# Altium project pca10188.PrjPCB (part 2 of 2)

## Sheet pca10188_sheet7_connectors.SchDoc: =BoardTitle+' - Connectors'
size A3; Organization: Nordic Semiconductor; DocumentNumber: 7; Revision: 0.7.0; SheetNumber: 7; SheetTotal: 7; Author: DABA; CompanyName: Nordic Semiconductor; DrawnBy: DABA; DocumentSize: A4
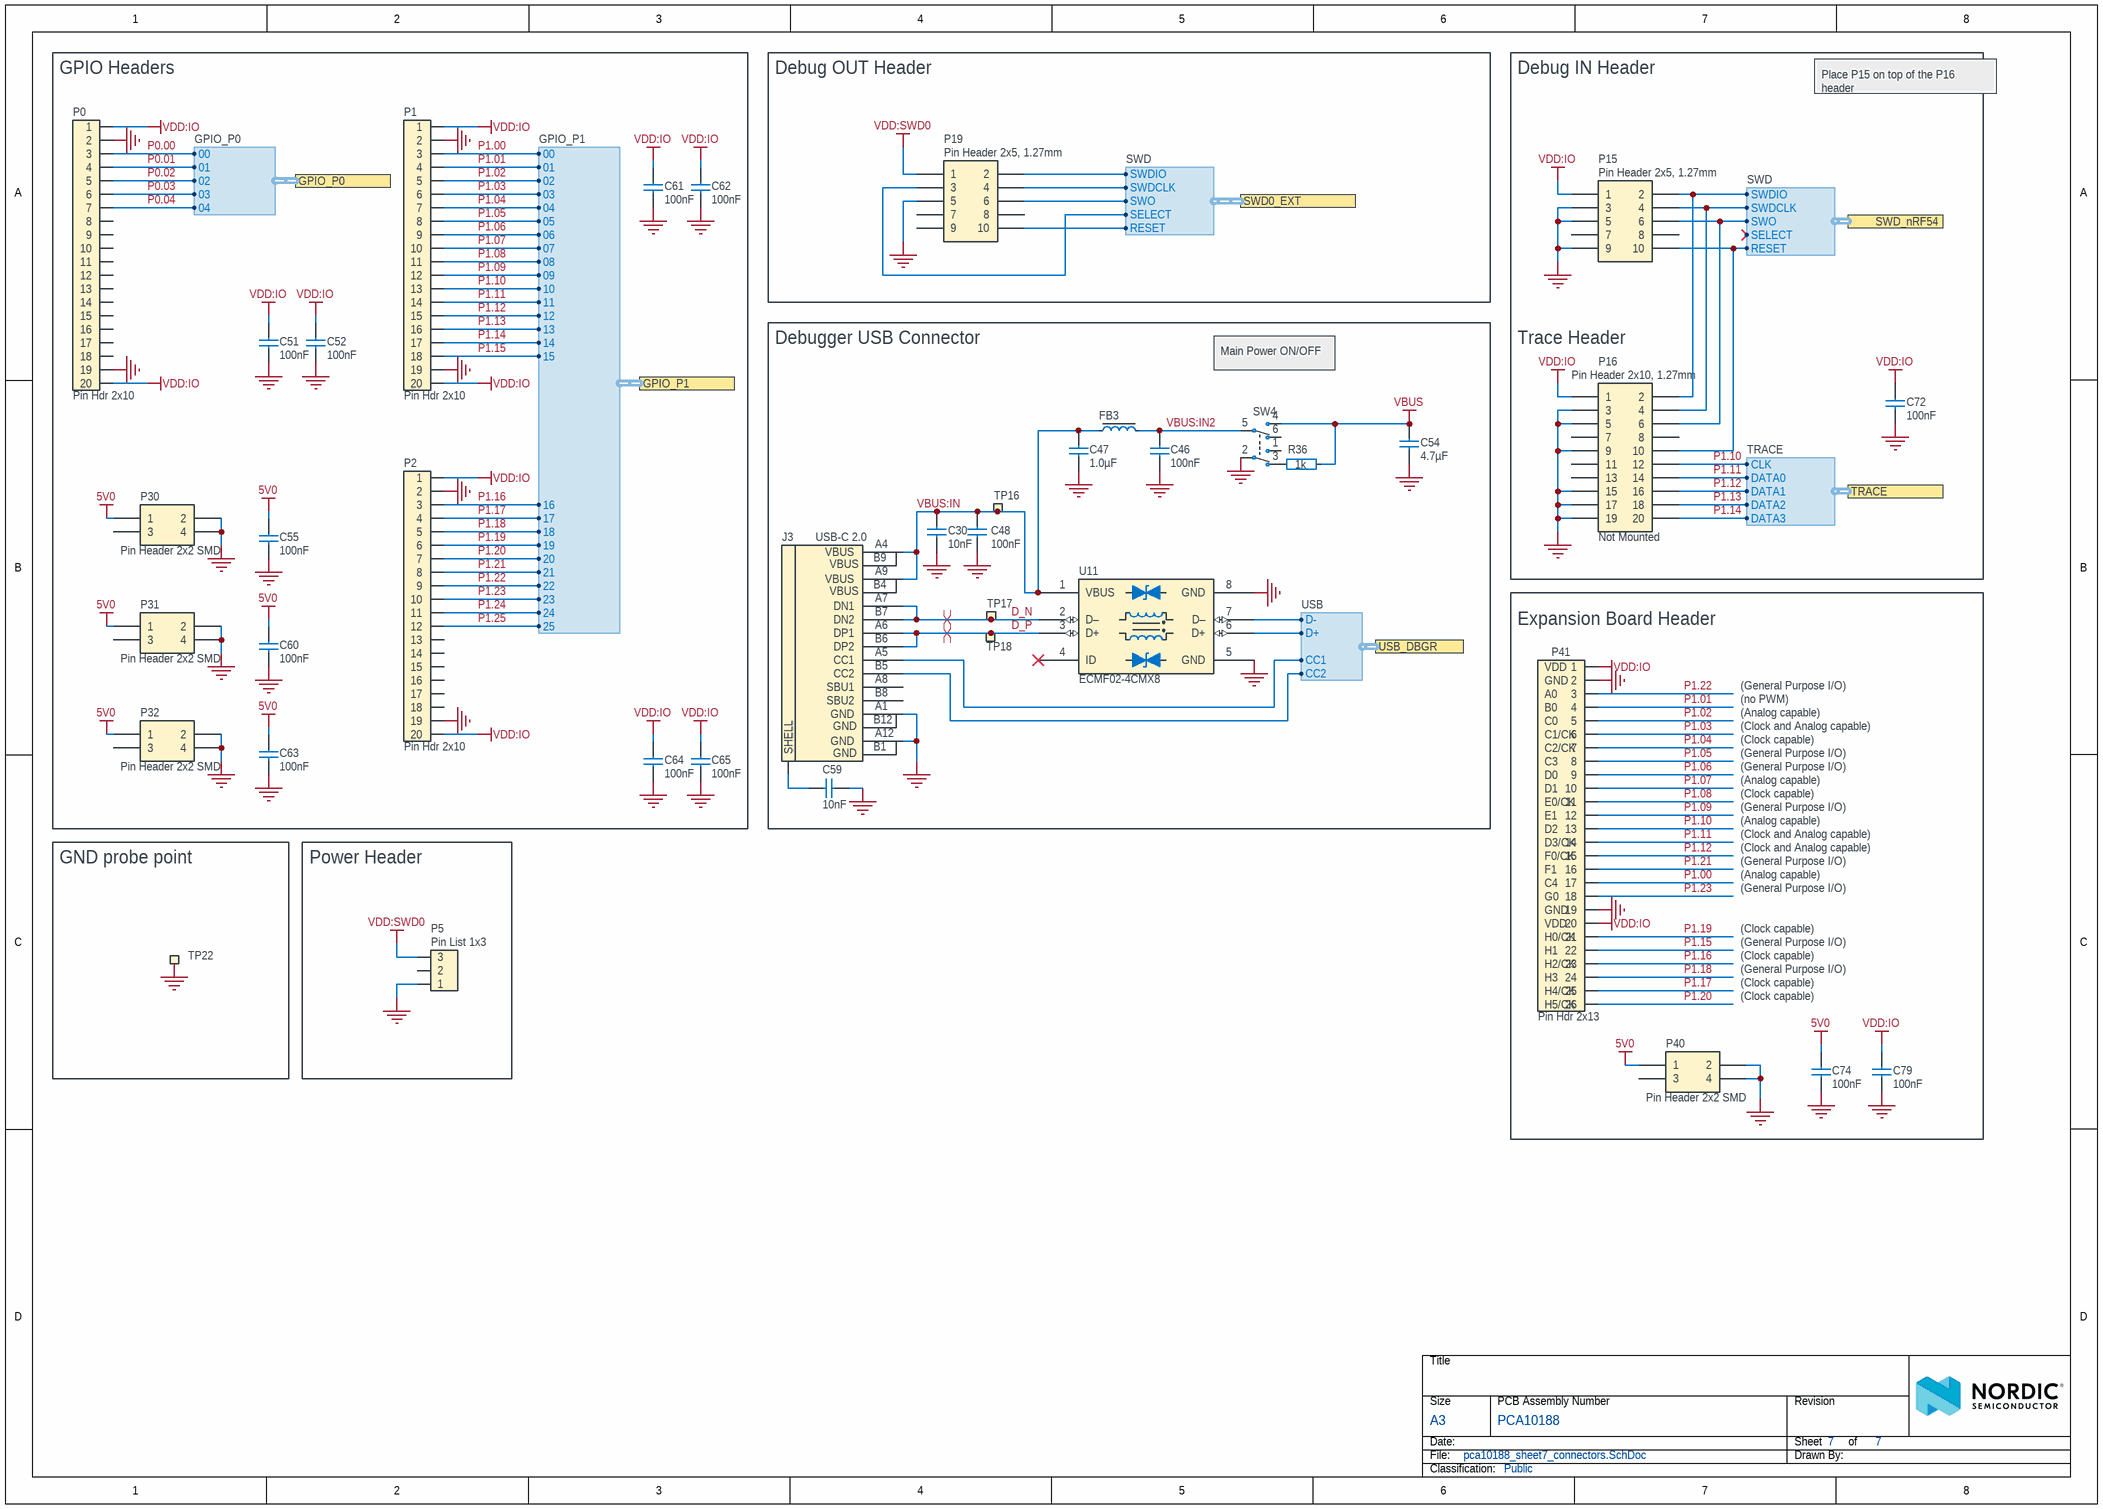
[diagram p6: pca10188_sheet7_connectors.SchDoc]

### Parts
C30  10nF  [CAPC0603X03L_C]
C46  100nF  [CAPC0603X03L_C]
C47  1.0µF  [CAPC1005X04L]
C48  100nF  [CAPC0603X03L_C]
C51  100nF  [CAPC0603X03L_C]
C52  100nF  [CAPC0603X03L_C]
C54  4.7µF  [CAPC1608X06L]
C55  100nF  [CAPC0603X03L_C]
C59  10nF  [CAPC1608X06L]
C60  100nF  [CAPC0603X03L_C]
C61  100nF  [CAPC0603X03L_C]
C62  100nF  [CAPC0603X03L_C]
C63  100nF  [CAPC0603X03L_C]
C64  100nF  [CAPC0603X03L_C]
C65  100nF  [CAPC0603X03L_C]
C72  100nF  [CAPC0603X03L_C]
C74  100nF  [CAPC0603X03L_C]
C79  100nF  [CAPC0603X03L_C]
FB3  120R/0.55A  [INDC1005X04L]  (value not drawn)
J3  USB-C 2.0  [SD-80259-001]
P0  Pin Hdr 2x10  [HDR_2x10-SMD]
P1  Pin Hdr 2x10  [HDR_2x10-SMD]
P2  Pin Hdr 2x10  [HDR_2x10-SMD]
P5  Pin List 1x3  [LIST_1x3_SMD]
P15  Pin Header 2x5, 1.27mm  [HDR_2x5-SMD-1.27mm-K]
P16  Pin Header 2x10, 1.27mm  Assembly: Not Mounted  [HDR_2x10-SMD-1.27mm-NC]
P19  Pin Header 2x5, 1.27mm  [HDR_2x5-SMD-1.27mm-K]
P30  Pin Header 2x2 SMD  [HDR_2x2-SMD]
P31  Pin Header 2x2 SMD  [HDR_2x2-SMD]
P32  Pin Header 2x2 SMD  [HDR_2x2-SMD]
P40  Pin Header 2x2 SMD  [HDR_2x2-SMD]
P41  Pin Hdr 2x13  [HDR_2x13-SMD]
R36  1k  [RESC0603X03L_C]
SW4  Switch  [JS102011JAQN]  (value not drawn)
TP16  Ø1.5mm,SMD  [TP_SMD_D1.5mm]  (value not drawn)  (no BOM)
TP17  Ø1.5mm,SMD  [TP_SMD_D1.5mm]  (value not drawn)  (no BOM)
TP18  Ø1.5mm,SMD  [TP_SMD_D1.5mm]  (value not drawn)  (no BOM)
TP22  TP  [S1751]  (value not drawn)
U11  ECMF02-4CMX8  [UFDFN50P120X250X55-8N]

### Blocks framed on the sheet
GPIO Headers: C51 C52 C55 C60-C65 P0-P2 P30-P32
Debug OUT Header: P19
Debugger USB Connector: C30 C46-C48 C54 C59 FB3 J3 R36 SW4 TP16-TP18 U11
Expansion Board Header: C74 C79 P40 P41
GND probe point: TP22
Power Header: P5

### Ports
GPIO_P0 (harness GPIO_P0), GPIO_P1 (harness GPIO_P1), SWD0_EXT (harness SWD), SWD_nRF54 (harness SWD), TRACE (harness TRACE), USB_DBGR (harness USB)

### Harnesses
SWD: SWDIO, SWDCLK, SWO, RESET, SELECT
TRACE: CLK, DATA0, DATA1, DATA3, DATA2
GPIO_P0: 02, 03, 04, 00, 01
USB: D+, D-, CC1, CC2
GPIO_P1: 00, 01, 02, 03, 04, 05, 06, 07, 08, 09, 10, 11, 12, 13, 14, 15, 21, 22, 16, 23, 17, 24, 18, 25, 19, 20

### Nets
5V0: C55.2 C60.2 C63.2 C74.2 P30.1 P31.1 P32.1 P40.1
GND: C30.2 C46.1 C47.1 C48.1 C51.1 C52.1 C54.2 C55.1 C59.2 C60.1 C61.1 C62.1 C63.1 C64.1 C65.1 C72.1 C74.1 C79.1 J3.A1(GND) J3.A12(GND) P0.2 P0.19 P1.2 P1.19 P2.2 P2.19 P5.1 P15.3 P15.5 P15.9 P16.3 P16.5 P16.9 P16.15 P16.17 P16.19 P19.5 P30.2 P30.4 P31.2 P31.4 P32.2 P32.4 P40.2 P40.4 P41.2 P41.19 SW4.2(COM-1) TP22.1 U11.5(GND) U11.8(GND)
VBUS: C54.1 R36.2 SW4.4(N.O-2)
VDD:IO: C51.2 C52.2 C61.2 C62.2 C64.2 C65.2 C72.2 C79.2 P0.1 P0.20 P1.1 P1.20 P2.1 P2.20 P15.1 P16.1 P41.1 P41.20
VDD:SWD0: P5.3 P19.1
D_N: J3.A7(DN1) J3.B7(DN2) TP17.1 U11.2(D–)
D_P: J3.A6(DP1) J3.B6(DP2) TP18.1 U11.3(D+)
DBGR_N: U11.7(D–) ; port USB_DBGR.D-
DBGR_P: U11.6(D+) ; port USB_DBGR.D+
nRF54_NRESET: P15.10 P16.10 ; port SWD_nRF54.RESET
P0.00: P0.3 ; port GPIO_P0.00
P0.01: P0.4 ; port GPIO_P0.01
P0.02: P0.5 ; port GPIO_P0.02
P0.03: P0.6 ; port GPIO_P0.03
P0.04: P0.7 ; port GPIO_P0.04
P1.00: P1.3 P41.17 ; port GPIO_P1.00
P1.01: P1.4 P41.4 ; port GPIO_P1.01
P1.02: P1.5 P41.5 ; port GPIO_P1.02
P1.03: P1.6 P41.6 ; port GPIO_P1.03
P1.04: P1.7 P41.7 ; port GPIO_P1.04
P1.05: P1.8 P41.8 ; port GPIO_P1.05
P1.06: P1.9 P41.9 ; port GPIO_P1.06
P1.07: P1.10 P41.10 ; port GPIO_P1.07
P1.08: P1.11 P41.11 ; port GPIO_P1.08
P1.09: P1.12 P41.12 ; port GPIO_P1.09
P1.10: P1.13 P16.12 P41.13 ; port TRACE.CLK, port GPIO_P1.10
P1.11: P1.14 P15.6 P16.6 P16.14 P41.14 ; port SWD_nRF54.SWO, port TRACE.DATA0, port GPIO_P1.11
P1.12: P1.15 P16.16 P41.15 ; port TRACE.DATA1, port GPIO_P1.12
P1.13: P1.16 P16.18 ; port TRACE.DATA2, port GPIO_P1.13
P1.14: P1.17 P16.20 ; port TRACE.DATA3, port GPIO_P1.14
P1.15: P1.18 P41.22 ; port GPIO_P1.15
P1.16: P2.3 P41.23 ; port GPIO_P1.16
P1.17: P2.4 P41.25 ; port GPIO_P1.17
P1.18: P2.5 P41.24 ; port GPIO_P1.18
P1.19: P2.6 P41.21 ; port GPIO_P1.19
P1.20: P2.7 P41.26 ; port GPIO_P1.20
P1.21: P2.8 P41.16 ; port GPIO_P1.21
P1.22: P2.9 P41.3 ; port GPIO_P1.22
P1.23: P2.10 P41.18 ; port GPIO_P1.23
P1.24: P2.11 ; port GPIO_P1.24
P1.25: P2.12 ; port GPIO_P1.25
SWD0_CLK_EXT: P19.4 ; port SWD0_EXT.SWDCLK
SWD0_IO_EXT: P19.2 ; port SWD0_EXT.SWDIO
SWD0_RESET_EXT: P19.10 ; port SWD0_EXT.RESET
SWD0_SEL: P19.3 ; port SWD0_EXT.SELECT
SWD0_SWO_EXT: P19.6 ; port SWD0_EXT.SWO
SWDCLK: P15.4 P16.4 ; port SWD_nRF54.SWDCLK
SWDIO: P15.2 P16.2 ; port SWD_nRF54.SWDIO
VBUS:IN: C30.1 C47.2 C48.2 FB3.1 J3.A4(VBUS) J3.A9(VBUS) TP16.1 U11.1(VBUS)
VBUS:IN2: C46.2 FB3.2 SW4.5(COM-2)
NetC59_1: C59.1 J3.SHLD(SHELL)
NetJ3_A5: J3.A5(CC1) ; port USB_DBGR.CC1
NetJ3_B5: J3.B5(CC2) ; port USB_DBGR.CC2
NetR36_1: R36.1 SW4.3(N.C-1)

Not connected (* = marked no-connect by the designer): J3 A8(SBU1) B8(SBU2); P0 8 9 10 11 12 13 14 15 16 17 18; P2 13 14 15 16 17 18; P5 2; P15 7 8; P16 7 8 11 13; P19 7 8 9; P30 3; P31 3; P32 3; P40 3; SW4 1(N.O-1) 6(N.C-2); U11 4(ID)*

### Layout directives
differential pair; differential pair class IMCU; net class IMCU_USB: D_N, D_P

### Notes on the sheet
- Debug IN Header
- Place P15 on top of the P16 header
- Main Power ON/OFF
- (near P16) Trace Header
- (near P41) VDD
- (near P41) GND
- (near P41) A0
- (near P41) B0
- (near P41) C0
- (Analog capable)
- (no PWM)
- (General Purpose I/O)
- (near P41) D0
- (near P41) D1
- (near P41) C1/CK
- (near P41) C2/CK
- (near P41) C3
- (Clock and Analog capable)
- (Clock capable)
- (near P41) E0/CK
- (near P41) E1
- (near P41) D2
- (near P41) D3/CK
- (near P41) F0/CK
- (near P41) F1
- (near P41) C4
- (near P41) G0
- (near P41) H0/CK
- (near P41) H1
- (near P41) H2/CK
- (near P41) H3
- (near P41) H4/CK
- (near P41) H5/CK

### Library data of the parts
C30 = C0201-10n: Capacitor, X7R, ±10%; Manufacturer: N.A.; Part number IPS: 00000003480; Part number Norautron: 26621779; Part number NEMS: 100200067; Note: 10V; Pad Count: 2; Component Status: Active
C46 C48 C51 C52 C55 C60-C65 C72 C74 C79 = C0201-100n: Capacitor, X5R, ±10%; Manufacturer: N.A.; Part number IPS: 00000001248, 00000002505; Part number Norautron: 262071862; Part number NEMS: 100200078; Note: 16V; Pad Count: 2; Component Status: Active
C47 = C0402-1µ0-16V-X5R: Capacitor, Ceramic, X5R, ±10%, 16V; Manufacturer: Murata; Manufacturer Part Number: GRT155R61C105KE01D; Part number NEMS: 100200452; Component Status: Active; Pad Count: 2; Artikkelnr Noca: N.A.
C54 = C0603-4µ7-10V-X7S: Capacitor, X7S, ±10%, 10V; Manufacturer: N.A.; Part number IPS: 00000001779; Part number NEMS: 100200351; Pad Count: 2; Artikkelnr Noca: 20030013; Component Status: Active
C59 = C0603-10n-100V-X7R: Capacitor, X7R, ±10%, 100V; Manufacturer: Murata; Manufacturer Part Number: GCM188R72A103KA37D; Part number NEMS: 100200349; Component Status: Active; Pad Count: 2; Artikkelnr Noca: N.A.
FB3 = FB0402-120R@100M-500mA: Ferrite Bead, 120 Ohm @ 100MHz, 500mA, 250 mOhm Max; Manufacturer: Murata; Manufacturer Part Number: BLM15AG121SN1D; Part number IPS: 00000009954; Part number Norautron: 265230631; Part number NEMS: 100300099; Note: Chip EMIFIL Inductor Type Chip Ferrite Bead; Artikkelnr Noca: 33029317; Pad Count: 2; Component Status: Active
J3 = 80259-1021: USB-C Receptacle, 16 Pin, USB 2.0; Manufacturer: Bellweather Electronic Corp.; Part number NEMS: 100500830; Component Status: Active; Pad Count: 16; Note: N.A.; System: Connector
P0-P2 = Pin Header 2x10 SMD, 2.54mm: Pin Header 2x10, 2.54mm (100mil) SMD; Manufacturer: WCON; Manufacturer Part Number: 1125-1210S0M116CR09; Part number NEMS: 100500738; Pad Count: 20; Artikkelnr Noca: N.A.; Component Status: Active; System: Connector
P5 = Pin List 1x3 SMD: Pin List 1x3, 2.54mm (100mil), SMD; Manufacturer: WCON; Manufacturer Part Number: 1125-1103S0M116CR04; Part number Norautron: 26470016; Part number NEMS: 100500306; Note: N.A.; Pad Count: 3; Component Status: Active; System: Connector
P15 P19 = Pin Header 2x5 SMD, 1.27mm, KS: Pin Header 2x5, 1.27mm (50mil), SMD, Keying Shroud; Manufacturer: WCON; Manufacturer Part Number: 3132-10MS0BK00R5; Part number NEMS: 100500261; Note: (Replaced 3132-10MS0BK00R1); Artikkelnr Noca: N.A.; Pad Count: 10; Component Status: Active; System: Connector
P16 = Pin Header 2x10 SMD, 1.27mm, KS, N.C.: Pin Header 2x10, 1.27mm (50mil), SMD, Keying Shroud; Manufacturer: WCON; Manufacturer Part Number: 3132-20MS0BK00R1; Part number NEMS: 100500279; Note: N.A.; Pad Count: 20; Component Status: Active; System: Connector
P30-P32 P40 = Pin Header 2x2 SMD: Pin Header 2x2, SMD, 2.54mm (100mil); Manufacturer: WCON; Manufacturer Part Number: 1125-1202S0M116CR03; Part number NEMS: 100500770; Component Status: Active; Pad Count: 4; Note: N.A.; System: Connector
P41 = Pin Header 2x13 SMD, 2.54mm: Pin Header 2x13, 2.54mm (100mil) SMD; Manufacturer: WCON; Manufacturer Part Number: 1125-1213S0M116CR09; Part number NEMS: 100500908; Component Status: Active; Pad Count: 26; Artikkelnr Noca: N.A.; System: Connector
R36 = R0201-1k0: Resistor, ±1%, 0.05W; Manufacturer: N.A.; Part number IPS: 00000005786; Part number NEMS: 100100043; Component Status: Active; Pad Count: 2; Note: Chip Res 1%
SW4 = Switch-Slide-RA-J-Lead-DPDT-8.5x3.5mm_C&K: SMD slide Switch (ON-ON); Manufacturer: C&K; Manufacturer Part Number: JS202011JAQN; Part number IPS: 00000007811; Part number NEMS: 101500037; Component Status: Active; Pad Count: 6; Note: N.A.
TP16-TP18 = TP_SMD_Ø1.5MM: 1.5mm circular SMD testpad; Manufacturer: Nordic Semiconductor; Manufacturer Part Number: N.A.; Part number NEMS: 100500477; Pad Count: 1; Component Status: Active
TP22 = TP - S1751-46R: PC TEST POINT TIN SMD L; Manufacturer: Harwin; Part number NEMS: 100500525; Component Status: Active; Pad Count: 1; Note: N.A.
U11 = ECMF02-4CMX8: 2 Line Common mode filter with ESD protection for USB 2.0 interface; Manufacturer: STMicroelectronics; Part number NEMS: 100800034; Component Status: NRND; Pad Count: 8; Note: N.A.

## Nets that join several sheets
5V0: pca10188_sheet3_debugger (R40.2), pca10188_sheet6_power_supply (13 pins), pca10188_sheet7_connectors (8 pins)
GND: pca10188_sheet2_nRF54LV10A (23 pins), pca10188_sheet3_debugger (31 pins), pca10188_sheet4_level_shifters (24 pins), pca10188_sheet5_misc (14 pins), pca10188_sheet6_power_supply (28 pins), pca10188_sheet7_connectors (51 pins)
VBUS: pca10188_sheet3_debugger (J4.5 R5.2), pca10188_sheet6_power_supply (C23.2 TP8.1 U10.21), pca10188_sheet7_connectors (C54.1 R36.2 SW4.4)
VDD:DBGR: pca10188_sheet3_debugger (29 pins), pca10188_sheet4_level_shifters (10 pins), pca10188_sheet6_power_supply (C29.1 U10.12)
VDD:IO: pca10188_sheet3_debugger (R46.2), pca10188_sheet4_level_shifters (7 pins), pca10188_sheet6_power_supply (5 pins), pca10188_sheet7_connectors (18 pins)
VDD:SWD0: pca10188_sheet4_level_shifters (C21.1 R18.2 U9.11), pca10188_sheet7_connectors (P5.3 P19.1)
VDDL:nRF: pca10188_sheet2_nRF54LV10A (5 pins), pca10188_sheet4_level_shifters (R51.1), pca10188_sheet5_misc (R23.2), pca10188_sheet6_power_supply (P6.2 R2.1 R48.1 TP1.1)
DBGR_BUTTON: pca10188_sheet1_cover_sheet (SB2.2), pca10188_sheet3_debugger (U2.AL27)
DBGR_N: pca10188_sheet3_debugger (U2.B4), pca10188_sheet7_connectors (U11.7)
DBGR_P: pca10188_sheet3_debugger (U2.B2), pca10188_sheet7_connectors (U11.6)
LED_PWR: pca10188_sheet5_misc (5 pins), pca10188_sheet6_power_supply (U10.31)
LED_PWR_CTRL: pca10188_sheet3_debugger (U2.A17), pca10188_sheet6_power_supply (U10.8)
NetJ3_A5: pca10188_sheet6_power_supply (U10.23), pca10188_sheet7_connectors (J3.A5)
NetJ3_B5: pca10188_sheet6_power_supply (U10.24), pca10188_sheet7_connectors (J3.B5)
nRF54_NRESET: pca10188_sheet1_cover_sheet (SB1.1), pca10188_sheet2_nRF54LV10A (P3.1 R1.2), pca10188_sheet4_level_shifters (U8.9), pca10188_sheet7_connectors (P15.10 P16.10)
P0.00: pca10188_sheet2_nRF54LV10A (U1.24), pca10188_sheet4_level_shifters (U4.9), pca10188_sheet7_connectors (P0.3)
P0.01: pca10188_sheet2_nRF54LV10A (U1.25), pca10188_sheet4_level_shifters (U4.3), pca10188_sheet7_connectors (P0.4)
P0.02: pca10188_sheet2_nRF54LV10A (U1.26), pca10188_sheet4_level_shifters (U4.13), pca10188_sheet7_connectors (P0.5)
P0.03: pca10188_sheet2_nRF54LV10A (U1.27), pca10188_sheet4_level_shifters (U4.6), pca10188_sheet7_connectors (P0.6)
P0.04: pca10188_sheet2_nRF54LV10A (U1.28), pca10188_sheet5_misc (SW6.2), pca10188_sheet7_connectors (P0.7)
P1.00: pca10188_sheet2_nRF54LV10A (U1.39), pca10188_sheet7_connectors (P1.3 P41.17)
P1.01: pca10188_sheet2_nRF54LV10A (U1.40), pca10188_sheet7_connectors (P1.4 P41.4)
P1.02: pca10188_sheet2_nRF54LV10A (U1.41), pca10188_sheet7_connectors (P1.5 P41.5)
P1.03: pca10188_sheet2_nRF54LV10A (U1.42), pca10188_sheet7_connectors (P1.6 P41.6)
P1.04: pca10188_sheet2_nRF54LV10A (U1.44), pca10188_sheet4_level_shifters (U6.9), pca10188_sheet7_connectors (P1.7 P41.7)
P1.05: pca10188_sheet2_nRF54LV10A (C41.2 U1.45), pca10188_sheet4_level_shifters (U6.3), pca10188_sheet7_connectors (P1.8 P41.8)
P1.06: pca10188_sheet2_nRF54LV10A (U1.43), pca10188_sheet4_level_shifters (U6.13), pca10188_sheet7_connectors (P1.9 P41.9)
P1.07: pca10188_sheet2_nRF54LV10A (U1.46), pca10188_sheet4_level_shifters (U6.6), pca10188_sheet7_connectors (P1.10 P41.10)
P1.08: pca10188_sheet2_nRF54LV10A (U1.37), pca10188_sheet5_misc (SW5.2), pca10188_sheet7_connectors (P1.11 P41.11)
P1.09: pca10188_sheet2_nRF54LV10A (U1.38), pca10188_sheet5_misc (SW3.2), pca10188_sheet7_connectors (P1.12 P41.12)
P1.10: pca10188_sheet2_nRF54LV10A (U1.47), pca10188_sheet5_misc (Q3.2 R11.1), pca10188_sheet7_connectors (P1.13 P16.12 P41.13)
P1.11: pca10188_sheet2_nRF54LV10A (U1.48), pca10188_sheet4_level_shifters (U8.13), pca10188_sheet7_connectors (5 pins)
P1.12: pca10188_sheet2_nRF54LV10A (U1.1), pca10188_sheet7_connectors (P1.15 P16.16 P41.15)
P1.13: pca10188_sheet2_nRF54LV10A (SB5.2), pca10188_sheet7_connectors (P1.16 P16.18)
P1.14: pca10188_sheet2_nRF54LV10A (SB6.2), pca10188_sheet7_connectors (P1.17 P16.20)
P1.15: pca10188_sheet2_nRF54LV10A (U1.4), pca10188_sheet7_connectors (P1.18 P41.22)
P1.16: pca10188_sheet2_nRF54LV10A (U1.5), pca10188_sheet7_connectors (P2.3 P41.23)
P1.17: pca10188_sheet2_nRF54LV10A (U1.6), pca10188_sheet7_connectors (P2.4 P41.25)
P1.18: pca10188_sheet2_nRF54LV10A (U1.7), pca10188_sheet7_connectors (P2.5 P41.24)
P1.19: pca10188_sheet2_nRF54LV10A (U1.8), pca10188_sheet7_connectors (P2.6 P41.21)
P1.20: pca10188_sheet2_nRF54LV10A (U1.9), pca10188_sheet7_connectors (P2.7 P41.26)
P1.21: pca10188_sheet2_nRF54LV10A (U1.10), pca10188_sheet5_misc (SW2.2), pca10188_sheet7_connectors (P2.8 P41.16)
P1.22: pca10188_sheet2_nRF54LV10A (U1.11), pca10188_sheet5_misc (Q3.5 R27.1), pca10188_sheet7_connectors (P2.9 P41.3)
P1.23: pca10188_sheet2_nRF54LV10A (U1.12), pca10188_sheet7_connectors (P2.10 P41.18)
P1.24: pca10188_sheet2_nRF54LV10A (U1.13), pca10188_sheet5_misc (Q2.2 R10.1), pca10188_sheet7_connectors (P2.11)
P1.25: pca10188_sheet2_nRF54LV10A (U1.23), pca10188_sheet5_misc (Q2.5 R12.1), pca10188_sheet7_connectors (P2.12)
RESET_BUTTON: pca10188_sheet1_cover_sheet (SB1.2 SB2.1), pca10188_sheet5_misc (SB8.1 SW1.2)
SWD0_CLK: pca10188_sheet3_debugger (U2.B18), pca10188_sheet4_level_shifters (U9.4)
SWD0_CLK_EXT: pca10188_sheet4_level_shifters (U9.8), pca10188_sheet7_connectors (P19.4)
SWD0_IO: pca10188_sheet3_debugger (U2.B16), pca10188_sheet4_level_shifters (U9.5)
SWD0_IO_EXT: pca10188_sheet4_level_shifters (U9.7), pca10188_sheet7_connectors (P19.2)
SWD0_RESET: pca10188_sheet3_debugger (U2.B22), pca10188_sheet4_level_shifters (U9.2)
SWD0_RESET_EXT: pca10188_sheet4_level_shifters (U9.10), pca10188_sheet7_connectors (P19.10)
SWD0_SEL: pca10188_sheet3_debugger (U2.B24), pca10188_sheet4_level_shifters (Q1.5), pca10188_sheet7_connectors (P19.3)
SWD0_SWO: pca10188_sheet3_debugger (U2.B20), pca10188_sheet4_level_shifters (U9.3)
SWD0_SWO_EXT: pca10188_sheet4_level_shifters (U9.9), pca10188_sheet7_connectors (P19.6)
SWD3_CLK: pca10188_sheet3_debugger (U2.R1), pca10188_sheet4_level_shifters (U7.2)
SWD3_CTRL: pca10188_sheet3_debugger (U2.AB2), pca10188_sheet4_level_shifters (R39.2 U8.1 U8.4 U8.11)
SWD3_IO: pca10188_sheet3_debugger (U2.N1), pca10188_sheet4_level_shifters (U7.3)
SWD3_RESET: pca10188_sheet3_debugger (U2.AA1), pca10188_sheet4_level_shifters (U7.4)
SWD3_SWO: pca10188_sheet3_debugger (U2.W1), pca10188_sheet4_level_shifters (U7.5)
SWDCLK: pca10188_sheet2_nRF54LV10A (U1.30), pca10188_sheet4_level_shifters (U8.3), pca10188_sheet7_connectors (P15.4 P16.4)
SWDIO: pca10188_sheet2_nRF54LV10A (U1.29), pca10188_sheet4_level_shifters (U8.6), pca10188_sheet7_connectors (P15.2 P16.2)
SWO_CTRL: pca10188_sheet3_debugger (U2.AJ1), pca10188_sheet4_level_shifters (R17.2 U8.15)
TWI0_SCL: pca10188_sheet3_debugger (U2.AF2), pca10188_sheet6_power_supply (U10.14)
TWI0_SDA: pca10188_sheet3_debugger (U2.AE1), pca10188_sheet6_power_supply (U10.13)
UART0_CTRL: pca10188_sheet3_debugger (U2.R31), pca10188_sheet4_level_shifters (R13.2 U3.12 U4.1 U4.4)
UART0_CTS: pca10188_sheet3_debugger (U2.AL9), pca10188_sheet4_level_shifters (U3.5)
UART0_HWFC: pca10188_sheet3_debugger (U2.AK16), pca10188_sheet4_level_shifters (R14.2 U4.11 U4.15)
UART0_RTS: pca10188_sheet3_debugger (U2.AL5), pca10188_sheet4_level_shifters (U3.3)
UART0_RxD: pca10188_sheet3_debugger (U2.AL19), pca10188_sheet4_level_shifters (U3.4)
UART0_TxD: pca10188_sheet3_debugger (U2.U31), pca10188_sheet4_level_shifters (U3.2)
UART1_CTRL: pca10188_sheet3_debugger (U2.AK18), pca10188_sheet4_level_shifters (R15.2 U5.12 U6.1 U6.4)
UART1_CTS: pca10188_sheet3_debugger (U2.AL15), pca10188_sheet4_level_shifters (U5.5)
UART1_HWFC: pca10188_sheet3_debugger (U2.AK20), pca10188_sheet4_level_shifters (R16.2 U6.11 U6.15)
UART1_RTS: pca10188_sheet3_debugger (U2.AL13), pca10188_sheet4_level_shifters (U5.3)
UART1_RxD: pca10188_sheet3_debugger (U2.AL21), pca10188_sheet4_level_shifters (U5.4)
UART1_TxD: pca10188_sheet3_debugger (U2.AL23), pca10188_sheet4_level_shifters (U5.2)

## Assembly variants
Default: not fitted C12 C41 C80 C81 P3 P4 P16 R22 R24 R31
